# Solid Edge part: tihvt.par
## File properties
Author: Argo
Template: Normal.par
Last saved by: Argo
Revision: 8
Application: Solid Edge
Material: Aluminum, 3004
Face Style: Aluminum
Fill Style: ANSI38(Aluminum)
Virtual Style: Polished aluminum
Coef. of Thermal Exp: 2.3e-05
Thermal Conductivity: 170.0
Specific Heat: 920.0
Modulus of Elasticity: 68947570000.0
Poission's Ratio: 0.33
Yield Stress: 68947570.0
Ultimate Stress: 179263682.0
Elongation: 0.0
Density: 2712,000 kg/m^3
Accuracy: 0,990
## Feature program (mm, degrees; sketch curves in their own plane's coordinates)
sketch for "unnamed Protrusion 1" plane through (0, 0, 0) normal (0, 0, 1) x-axis (1, 0, 0)
  circle centre (0, 0) radius 1.5
extrude "unnamed Protrusion 1" add finite 1 along +normal
sketch for "ExtrudedProtrusion_2" plane through (0, 0, 0) normal (0, 0, -1) x-axis (1, 0, 0)
  circle centre (0, 0) radius 1
extrude "ExtrudedProtrusion_2" add finite 4 along +normal
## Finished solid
Body 1: solid body, 5 faces, 4 edges, 0 vertices.
  Faces by surface: plane 3, cylinder 2
  Edges by curve: circle 4
Bounding box of the edges (mm): 3.000 x 3.000 x 5.000, from (-1.5, -1.5, -4) to (1.5, 1.5, 1).
Cylindrical faces by radius (mm): R1 x1, R1.5 x1
Planar faces by outward normal: +z 1, -z 2
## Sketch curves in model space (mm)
circle centre (0, 0, 0) radius 1
circle centre (0, 0, 0) radius 1.5
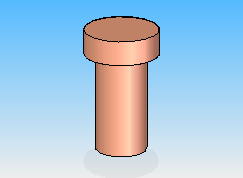
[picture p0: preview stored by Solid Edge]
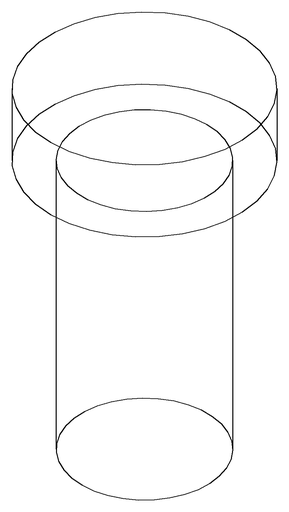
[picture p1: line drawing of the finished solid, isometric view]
